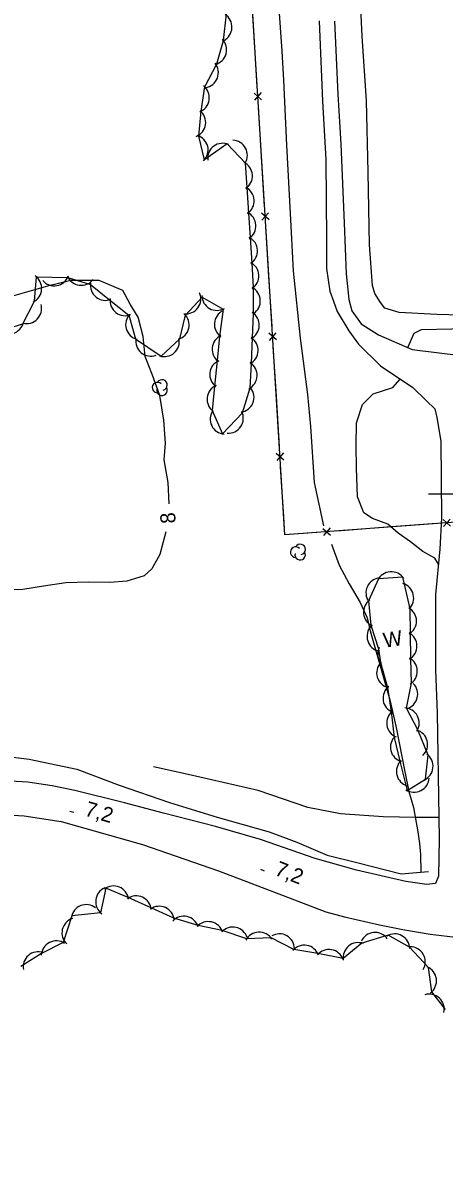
# Model space of a CAD drawing. Extents: x 643342 to 646936, y 5873857 to 5876103.
# Drawn here: x 645909.1 to 645993.2, y 5874668.3 to 5874894 of the extents above; entities that cross this region are included whole.
import ezdxf

# ---------------------------------------------------------------- set-up
doc = ezdxf.new("R2010")
doc.units = 0
for name, color, linetype in [('Niveau 2', 7, 'Continuous'), ('Niveau 21', 7, 'Continuous'), ('Niveau 22', 7, 'Continuous'), ('Niveau 3', 7, 'Continuous'), ('Niveau 33', 7, 'Continuous'), ('Niveau 37', 7, 'Continuous'), ('Niveau 4', 7, 'Continuous'), ('Niveau 44', 7, 'Continuous'), ('Niveau 61', 7, 'Continuous')]:
    doc.layers.add(name, color=color, linetype=linetype)

msp = doc.modelspace()

# ---------------------------------------------------------------- linework, layer by layer
at = {"layer": 'Niveau 2'}
for points in [[(645985.93, 5874829.16), (645987.13, 5874832.05), (645988.65, 5874832.74), (645994.65, 5874832.87), (646001.66, 5874833.42), (646008.42, 5874833.43), (646014.78, 5874834.11), (646019.28, 5874834.02), (646026.81, 5874833.85), (646031.77, 5874833.73), (646037.26, 5874833.59), (646041.91, 5874833.8), (646046.66, 5874834.14), (646048.75, 5874834.28), (646049.86, 5874834.89), (646051.31, 5874836.57), (646051.97, 5874839.3), (646052.28, 5874844.45), (646051.99, 5874857.32), (646051.63, 5874866.57), (646051.17, 5874880.07), (646050.57, 5874891.69), (646049.18, 5874905.3)], [(645938.32, 5874797.98), (645938.1, 5874802.24), (645937.34, 5874806.8), (645937.57, 5874810.09), (645937.27, 5874814.68), (645936.43, 5874819.59), (645935.01, 5874823.64), (645933.5, 5874827.38), (645933.14, 5874831.39), (645932.15, 5874835.23), (645930.55, 5874837.81), (645929.05, 5874840.56), (645924.35, 5874842.57), (645918.74, 5874842.53), (645914.04, 5874841.38), (645905.69, 5874839.04)], [(645991.98, 5874785.95), (645991.26, 5874787.15), (645988.89, 5874788.5), (645986.46, 5874790.43), (645984, 5874792.18), (645981.93, 5874793.96), (645978.87, 5874795.09), (645977.15, 5874796.19), (645975.86, 5874799.43), (645975.65, 5874805.2), (645975.61, 5874809.58), (645975.67, 5874814.14), (645976.84, 5874817.84), (645978.96, 5874819.92), (645982.89, 5874821.18), (645984.38, 5874822.86)], [(645937.66, 5874792.42), (645936.45, 5874787.87), (645934.86, 5874785.01), (645933.33, 5874783.67), (645929.85, 5874782.61), (645926.48, 5874782.31), (645922.16, 5874782.36), (645917.73, 5874782.22), (645913.28, 5874781.55), (645909.12, 5874780.91), (645903.76, 5874780.7)]]:
    msp.add_lwpolyline(points, dxfattribs=at)
at = {"layer": 'Niveau 21'}
for points in [[(645968.22, 5874894.35), (645968.86, 5874878.28), (645969.52, 5874866.66), (645969.69, 5874850.67), (645969.66, 5874844.95), (645970.35, 5874840.44), (645971.09, 5874838.39), (645971.83, 5874836.34), (645974.11, 5874832.53), (645976.06, 5874829.87), (645980.48, 5874825.51)], [(645971.28, 5874894.25), (645971.92, 5874879.71), (645972.57, 5874869.71), (645973.19, 5874854), (645973.61, 5874843.87), (645974.12, 5874838.77), (645974.76, 5874836.47), (645976.59, 5874833.92), (645980.03, 5874831.71), (645986.78, 5874828.8), (645996.44, 5874827.61)], [(645980.48, 5874825.51), (645986.88, 5874821.17), (645989.64, 5874818.56), (645991.28, 5874816.93), (645991.65, 5874815.2), (645992.48, 5874810.47), (645992.6, 5874795.18), (645992.25, 5874788.97), (645991.43, 5874779.92), (645991.42, 5874764.85), (645991.72, 5874756.34), (645992.06, 5874735.44), (645992.13, 5874731.12), (645991.99, 5874723.74), (645991.4, 5874722.29), (645989.67, 5874722.05), (645985.53, 5874722.69), (645975.67, 5874724.91), (645967.43, 5874727.25), (645956.51, 5874731.03), (645947.54, 5874733.67), (645937.17, 5874736.32), (645929.42, 5874738.35), (645919.53, 5874740.8), (645915.01, 5874741.77), (645910.16, 5874742.48), (645902.06, 5874742.95)], [(645734.03, 5874661.49), (645747.15, 5874668.6), (645761.6, 5874677.24), (645774.6, 5874684.96), (645790.1, 5874693.56), (645804.86, 5874701.17), (645820.98, 5874709.46), (645836.3, 5874717.34), (645848.46, 5874723.71), (645854.48, 5874726.13), (645862.13, 5874728.66), (645869.34, 5874730.7), (645876.01, 5874732.23), (645886.75, 5874734.16), (645894.6, 5874735.42), (645900.52, 5874736.08), (645904.96, 5874736.04), (645909.43, 5874735.78), (645916.76, 5874734.66)], [(645916.76, 5874734.66), (645933.01, 5874730.08), (645948.14, 5874724.84), (645961.02, 5874719.91), (645969.56, 5874716.66), (645973.26, 5874715.64), (645980.28, 5874714.04), (645984.91, 5874713.08), (645990.35, 5874712.18), (645996, 5874711.53), (645997.68, 5874710.95), (645999.85, 5874708.53), (646003.25, 5874703.75), (646003.92, 5874701.11), (646005.24, 5874693.02), (646006.92, 5874683.31), (646007.76, 5874673.9), (646008.52, 5874663.89)]]:
    msp.add_lwpolyline(points, dxfattribs=at)
at = {"layer": 'Niveau 22'}
msp.add_lwpolyline([(645992.06, 5874735.44), (645987.5, 5874735.46), (645980.95, 5874735.58), (645972.5, 5874736.15), (645965.98, 5874737.44), (645956.03, 5874740.82), (645942.11, 5874744.04), (645935.22, 5874745.54)], dxfattribs=at)
at = {"layer": 'Niveau 3'}
for p, q in [((645918.54, 5874736.74), (645919.31, 5874736.51)), ((645956.49, 5874725.13), (645957.23, 5874724.84))]:
    msp.add_line(p, q, dxfattribs=at)
at = {"layer": 'Niveau 33'}
msp.add_lwpolyline([(645996.49, 5874835.65), (645991.69, 5874835.78), (645984.19, 5874836.19), (645981.32, 5874837.04), (645980.42, 5874838.14), (645979.35, 5874839.94), (645978.87, 5874841.54), (645978.25, 5874849.68), (645977.96, 5874864.15), (645977.69, 5874878.38), (645976.82, 5874891.29), (645976, 5874908.17)], dxfattribs=at)
at = {"layer": 'Niveau 37'}
for points in [[(646152.66, 5875016.23), (646179.19, 5874807.95), (645961.38, 5874791.81), (645948.36, 5875003.47), (646152.66, 5875016.23)], [(645955.26, 5874891.24), (645954.65, 5874901.22)], [(645955.88, 5874881.26), (645955.26, 5874891.24)], [(645956.75, 5874878.6), (645955.25, 5874879.92)], [(645956.66, 5874880.01), (645955.34, 5874878.51)], [(645956.74, 5874867.28), (645956.12, 5874877.26)], [(645957.35, 5874857.3), (645956.74, 5874867.28)], [(645958.22, 5874854.64), (645956.72, 5874855.97)], [(645958.14, 5874856.06), (645956.81, 5874854.56)], [(645958.21, 5874843.33), (645957.6, 5874853.31)], [(645958.82, 5874833.35), (645958.21, 5874843.33)], [(645959.7, 5874830.69), (645958.2, 5874832.02)], [(645959.61, 5874832.1), (645958.28, 5874830.6)], [(645959.68, 5874819.38), (645959.07, 5874829.36)], [(645960.3, 5874809.4), (645959.68, 5874819.38)], [(645961.17, 5874806.74), (645959.67, 5874808.06)], [(645961.08, 5874808.15), (645959.76, 5874806.65)], [(645961.16, 5874795.42), (645960.54, 5874805.4)], [(645967.74, 5874792.29), (645961.38, 5874791.81), (645961.16, 5874795.42)], [(645992.91, 5874794.86), (645994.43, 5874793.55)], [(645994.33, 5874794.97), (645993.02, 5874793.45)], [(645968.98, 5874793.09), (645970.5, 5874791.78)], [(645970.39, 5874793.19), (645969.09, 5874791.68)], [(645981.71, 5874793.32), (645971.73, 5874792.58)], [(645991.68, 5874794.06), (645981.71, 5874793.32)]]:
    msp.add_lwpolyline(points, dxfattribs=at)
at = {"layer": 'Niveau 4'}
for points in [[(645969.12, 5874793.6), (645967.29, 5874802.24), (645966.56, 5874813.41), (645965.95, 5874819.8), (645964.51, 5874831.04), (645963.13, 5874844.5), (645962.49, 5874855.91), (645961.8, 5874869.54), (645961.16, 5874882.48), (645960.84, 5874888.3), (645959.94, 5874901.56)], [(645970.68, 5874789.94), (645972.2, 5874785.74), (645974.2, 5874782.02), (645976.4, 5874778.32), (645977.81, 5874775.28), (645978.39, 5874772.65), (645980.93, 5874763.81), (645982.31, 5874758.91), (645983.56, 5874753.42), (645985.31, 5874744.55), (645986.12, 5874740.63), (645987, 5874737.44), (645987.89, 5874732.59), (645988.21, 5874730.23), (645988.41, 5874728.05), (645988.5, 5874724.52)], [(645901.77, 5874748.11), (645910.39, 5874747.08), (645919.89, 5874745.07), (645928.32, 5874741.92), (645938.4, 5874738.43), (645947.86, 5874735.48), (645958.25, 5874732.59), (645963.78, 5874730.53), (645969.82, 5874727.92), (645976.02, 5874726.37), (645984.6, 5874724.18), (645990.04, 5874724.66)]]:
    msp.add_lwpolyline(points, dxfattribs=at)
at = {"layer": 'Niveau 44'}
for points in [[(645904.52, 5874832.49), (645909.17, 5874833.88), (645911.46, 5874838.42), (645911.85, 5874843.26), (645918.09, 5874843.15), (645922.63, 5874841.74), (645926.4, 5874838.69), (645930.27, 5874835.61), (645931.58, 5874830.93), (645936.69, 5874827.44), (645940.46, 5874830.92), (645941.57, 5874835.65), (645944.86, 5874839.24), (645949.08, 5874836.84), (645948.34, 5874831.39), (645947.91, 5874826.56), (645947.38, 5874821.44), (645946.87, 5874816.62), (645948.95, 5874811.94), (645952.92, 5874816.12), (645954.49, 5874821.13), (645954.71, 5874825.98), (645954.94, 5874831.12), (645955.15, 5874835.97), (645955.11, 5874841.13), (645954.84, 5874845.98), (645954.54, 5874851.12), (645954.2, 5874855.96), (645953.84, 5874861.09), (645953.51, 5874865.94), (645949.89, 5874869.77), (645945.36, 5874866.64), (645944.22, 5874871.36), (645944.72, 5874876.34), (645945.42, 5874881.14), (645947.82, 5874885.75), (645949.12, 5874890.43), (645949.75, 5874895.71)], [(645985.76, 5874740.82), (645989.43, 5874743.06), (645989.93, 5874747.88), (645987.86, 5874752.96), (645985.6, 5874757.26), (645986.6, 5874762.23), (645986.52, 5874767.08), (645986.44, 5874772.22), (645986.36, 5874777.08), (645985.22, 5874782), (645984.89, 5874783.38), (645980.05, 5874783.04), (645978.07, 5874778.64), (645978.52, 5874773.81), (645980.07, 5874769.06), (645980.45, 5874766.36), (645981.85, 5874761.38), (645982.57, 5874756.58), (645983.14, 5874751.43), (645984.3, 5874746.71), (645985.49, 5874741.86), (645985.76, 5874740.82)], [(645993.38, 5874697.15), (645990.67, 5874700.68), (645990.05, 5874705.5), (645986.25, 5874709.61), (645982, 5874711.95), (645976.72, 5874710.4), (645972.99, 5874707.3), (645967.95, 5874708.29), (645963.17, 5874709.13), (645958.62, 5874711.44), (645953.77, 5874711.24), (645948.86, 5874712.88), (645944.12, 5874713.92), (645939.26, 5874715.34), (645934.84, 5874717.35), (645930.15, 5874719.49), (645925.67, 5874721.35), (645924.63, 5874716.45), (645918.88, 5874715.82), (645917.2, 5874710.5), (645912.86, 5874708.33), (645908.77, 5874705.76)]]:
    msp.add_lwpolyline(points, dxfattribs=at)
for centre, radius, start, end in [((645947.83, 5874893.09), 3, 297.2628, 57.2408), ((645947.83, 5874893.09), 3, 297.2628, 57.2408), ((645947.83, 5874893.09), 3, 297.2628, 57.2408), ((645946.77, 5874888.56), 3, 284.3767, 44.3547), ((645946.77, 5874888.56), 3, 284.3767, 44.3547), ((645946.77, 5874888.56), 3, 284.3767, 44.3547), ((645945.13, 5874884.01), 3, 278.5152, 38.4932), ((645945.13, 5874884.01), 3, 278.5152, 38.4932), ((645945.13, 5874884.01), 3, 278.5152, 38.4932), ((645943.32, 5874879), 3, 291.6549, 51.6328), ((645943.32, 5874879), 3, 291.6549, 51.6328), ((645943.32, 5874879), 3, 291.6549, 51.6328), ((645942.6, 5874874.05), 3, 291.6549, 51.6328), ((645942.6, 5874874.05), 3, 291.6549, 51.6328), ((645942.6, 5874874.05), 3, 291.6549, 51.6328), ((645943.08, 5874868.59), 3, 313.5793, 73.5572), ((645943.08, 5874868.59), 3, 313.5793, 73.5572), ((645943.08, 5874868.59), 3, 313.5793, 73.5572), ((645948.99, 5874866.91), 3, 66.4997, 186.4776), ((645948.99, 5874866.91), 3, 66.4997, 186.4776), ((645948.99, 5874866.91), 3, 66.4997, 186.4776), ((645950.91, 5874867.53), 3, 328.533, 88.5109), ((645950.91, 5874867.53), 3, 328.533, 88.5109), ((645950.91, 5874867.53), 3, 328.533, 88.5109), ((645951.92, 5874863.39), 3, 303.9903, 63.9682), ((645951.92, 5874863.39), 3, 303.9903, 63.9682), ((645951.92, 5874863.39), 3, 303.9903, 63.9682), ((645952.26, 5874858.4), 3, 303.9903, 63.9682), ((645952.26, 5874858.4), 3, 303.9903, 63.9682), ((645952.26, 5874858.4), 3, 303.9903, 63.9682), ((645952.61, 5874853.42), 3, 303.9903, 63.9682), ((645952.61, 5874853.42), 3, 303.9903, 63.9682), ((645952.61, 5874853.42), 3, 303.9903, 63.9682), ((645952.94, 5874848.45), 3, 303.2077, 63.1856), ((645952.94, 5874848.45), 3, 303.2077, 63.1856), ((645952.94, 5874848.45), 3, 303.2077, 63.1856), ((645953.21, 5874843.46), 3, 303.2077, 63.1856), ((645953.21, 5874843.46), 3, 303.2077, 63.1856), ((645953.21, 5874843.46), 3, 303.2077, 63.1856), ((645909.9, 5874840.98), 3, 295.33, 55.308), ((645909.9, 5874840.98), 3, 295.33, 55.308), ((645909.9, 5874840.98), 3, 295.33, 55.308), ((645915.4, 5874844.48), 3, 219.7542, 339.7322), ((645915.4, 5874844.48), 3, 219.7542, 339.7322), ((645915.4, 5874844.48), 3, 219.7542, 339.7322), ((645920.8, 5874844.59), 3, 201.9481, 321.9261), ((645920.8, 5874844.59), 3, 201.9481, 321.9261), ((645920.8, 5874844.59), 3, 201.9481, 321.9261), ((645925.62, 5874841.58), 3, 170.9659, 290.9438), ((645925.62, 5874841.58), 3, 170.9659, 290.9438), ((645925.62, 5874841.58), 3, 170.9659, 290.9438), ((645941.63, 5874838.89), 3, 263.0045, 22.9825), ((645941.63, 5874838.89), 3, 263.0045, 22.9825), ((645941.63, 5874838.89), 3, 263.0045, 22.9825), ((645953.49, 5874838.46), 3, 303.2077, 63.1856), ((645953.49, 5874838.46), 3, 303.2077, 63.1856), ((645953.49, 5874838.46), 3, 303.2077, 63.1856), ((645909.88, 5874836.95), 3, 255.3918, 15.3698), ((645909.88, 5874836.95), 3, 255.3918, 15.3698), ((645909.88, 5874836.95), 3, 255.3918, 15.3698), ((645929.53, 5874838.52), 3, 172.2624, 292.2403), ((645929.53, 5874838.52), 3, 172.2624, 292.2403), ((645929.53, 5874838.52), 3, 172.2624, 292.2403), ((645947.84, 5874839.57), 3, 180.4297, 300.4076), ((645947.84, 5874839.57), 3, 180.4297, 300.4076), ((645947.84, 5874839.57), 3, 180.4297, 300.4076), ((645932.63, 5874833.75), 3, 135.6691, 255.6471), ((645932.63, 5874833.75), 3, 135.6691, 255.6471), ((645932.63, 5874833.75), 3, 135.6691, 255.6471), ((645939.3, 5874833.69), 3, 286.7798, 46.7577), ((645939.3, 5874833.69), 3, 286.7798, 46.7577), ((645939.3, 5874833.69), 3, 286.7798, 46.7577), ((645950.32, 5874833.8), 3, 114.9218, 234.8998), ((645950.32, 5874833.8), 3, 114.9218, 234.8998), ((645950.32, 5874833.8), 3, 114.9218, 234.8998), ((645953.28, 5874833.62), 3, 297.49, 57.4679), ((645953.28, 5874833.62), 3, 297.49, 57.4679), ((645953.28, 5874833.62), 3, 297.49, 57.4679), ((645906.34, 5874834.87), 3, 226.6735, 346.6514), ((645906.34, 5874834.87), 3, 226.6735, 346.6514), ((645906.34, 5874834.87), 3, 226.6735, 346.6514), ((645934.65, 5874830.45), 3, 170.6479, 290.6258), ((645934.65, 5874830.45), 3, 170.6479, 290.6258), ((645934.65, 5874830.45), 3, 170.6479, 290.6258), ((645937.34, 5874830.36), 3, 251.5009, 11.4789), ((645937.34, 5874830.36), 3, 251.5009, 11.4789), ((645937.34, 5874830.36), 3, 251.5009, 11.4789), ((645949.88, 5874828.82), 3, 114.9218, 234.8998), ((645949.88, 5874828.82), 3, 114.9218, 234.8998), ((645949.88, 5874828.82), 3, 114.9218, 234.8998), ((645953.06, 5874828.62), 3, 297.49, 57.4679), ((645953.06, 5874828.62), 3, 297.49, 57.4679), ((645953.06, 5874828.62), 3, 297.49, 57.4679), ((645949.41, 5874823.81), 3, 113.9485, 233.9264), ((645949.41, 5874823.81), 3, 113.9485, 233.9264), ((645949.41, 5874823.81), 3, 113.9485, 233.9264), ((645952.84, 5874823.63), 3, 297.49, 57.4679), ((645952.84, 5874823.63), 3, 297.49, 57.4679), ((645952.84, 5874823.63), 3, 297.49, 57.4679), ((645935.98, 5874821.18), 1.05, 44.1154, 269.804), ((645936.88, 5874821.71), 1.05, 282.2692, 149.7263), ((645948.88, 5874818.84), 3, 113.9485, 233.9264), ((645948.88, 5874818.84), 3, 113.9485, 233.9264), ((645948.88, 5874818.84), 3, 113.9485, 233.9264), ((645936.88, 5874820.66), 1.05, 166.9369, 29.6212), ((645952.23, 5874819.24), 3, 277.7816, 37.7595), ((645952.23, 5874819.24), 3, 277.7816, 37.7595), ((645952.23, 5874819.24), 3, 277.7816, 37.7595), ((645949.5, 5874814.89), 3, 145.482, 265.4599), ((645949.5, 5874814.89), 3, 145.482, 265.4599), ((645949.5, 5874814.89), 3, 145.482, 265.4599), ((645950.1, 5874815.08), 3, 266.1343, 26.1122), ((645950.1, 5874815.08), 3, 266.1343, 26.1122), ((645950.1, 5874815.08), 3, 266.1343, 26.1122), ((645964.43, 5874788.91), 1.05, 282.2692, 149.7263), ((645963.53, 5874788.38), 1.05, 44.1154, 269.804), ((645964.43, 5874787.86), 1.05, 166.9369, 29.6212), ((645980.55, 5874780.25), 3, 95.1112, 215.0891), ((645980.55, 5874780.25), 3, 95.1112, 215.0891), ((645980.55, 5874780.25), 3, 95.1112, 215.0891), ((645982.59, 5874781.45), 3, 34.0714, 154.0494), ((645982.59, 5874781.45), 3, 34.0714, 154.0494), ((645982.59, 5874781.45), 3, 34.0714, 154.0494), ((645984.07, 5874779.23), 3, 313.5818, 73.5598), ((645984.07, 5874779.23), 3, 313.5818, 73.5598), ((645984.07, 5874779.23), 3, 313.5818, 73.5598), ((645980.05, 5874776.39), 3, 125.3144, 245.2924), ((645980.05, 5874776.39), 3, 125.3144, 245.2924), ((645980.05, 5874776.39), 3, 125.3144, 245.2924), ((645984.63, 5874774.62), 3, 300.9414, 60.9194), ((645984.63, 5874774.62), 3, 300.9414, 60.9194), ((645984.63, 5874774.62), 3, 300.9414, 60.9194), ((645980.76, 5874771.58), 3, 130.4514, 250.4294), ((645980.76, 5874771.58), 3, 130.4514, 250.4294), ((645980.76, 5874771.58), 3, 130.4514, 250.4294), ((645984.71, 5874769.62), 3, 300.9414, 60.9194), ((645984.71, 5874769.62), 3, 300.9414, 60.9194), ((645984.71, 5874769.62), 3, 300.9414, 60.9194), ((645982.91, 5874768.09), 3, 155.1287, 219.2992), ((645982.91, 5874768.09), 3, 155.1287, 219.2992), ((645982.91, 5874768.09), 3, 155.1287, 219.2992), ((645982.68, 5874764.29), 3, 136.8898, 256.8678), ((645982.68, 5874764.29), 3, 136.8898, 256.8678), ((645982.68, 5874764.29), 3, 136.8898, 256.8678), ((645984.79, 5874764.62), 3, 300.9414, 60.9194), ((645984.79, 5874764.62), 3, 300.9414, 60.9194), ((645984.79, 5874764.62), 3, 300.9414, 60.9194), ((645983.95, 5874759.24), 3, 128.5117, 248.4897), ((645983.95, 5874759.24), 3, 128.5117, 248.4897), ((645983.95, 5874759.24), 3, 128.5117, 248.4897), ((645984.87, 5874760.04), 3, 285.2965, 45.2745), ((645984.87, 5874760.04), 3, 285.2965, 45.2745), ((645984.87, 5874760.04), 3, 285.2965, 45.2745), ((645984.69, 5874754.3), 3, 128.5117, 248.4897), ((645984.69, 5874754.3), 3, 128.5117, 248.4897), ((645984.69, 5874754.3), 3, 128.5117, 248.4897), ((645985.17, 5874754.29), 3, 327.6951, 87.673), ((645985.17, 5874754.29), 3, 327.6951, 87.673), ((645985.17, 5874754.29), 3, 327.6951, 87.673), ((645985.43, 5874749.49), 3, 133.8311, 253.8091), ((645985.43, 5874749.49), 3, 133.8311, 253.8091), ((645985.43, 5874749.49), 3, 133.8311, 253.8091), ((645986.84, 5874750), 3, 313.8317, 73.8097), ((645986.84, 5874750), 3, 313.8317, 73.8097), ((645986.84, 5874750), 3, 313.8317, 73.8097), ((645987.92, 5874745.65), 3, 294.097, 54.0749), ((645987.92, 5874745.65), 3, 294.097, 54.0749), ((645987.92, 5874745.65), 3, 294.097, 54.0749), ((645986.62, 5874744.64), 3, 133.8311, 253.8091), ((645986.62, 5874744.64), 3, 133.8311, 253.8091), ((645986.62, 5874744.64), 3, 133.8311, 253.8091), ((645987.15, 5874743.49), 3, 236.5526, 356.5305), ((645987.15, 5874743.49), 3, 236.5526, 356.5305), ((645987.15, 5874743.49), 3, 236.5526, 356.5305), ((645926.66, 5874718.66), 3, 113.4098, 233.3877), ((645926.66, 5874718.66), 3, 113.4098, 233.3877), ((645926.66, 5874718.66), 3, 113.4098, 233.3877), ((645927.24, 5874718.79), 3, 7.5654, 127.5434), ((645927.24, 5874718.79), 3, 7.5654, 127.5434), ((645927.24, 5874718.79), 3, 7.5654, 127.5434), ((645921.78, 5874715.07), 3, 51.5013, 171.4792), ((645921.78, 5874715.07), 3, 51.5013, 171.4792), ((645921.78, 5874715.07), 3, 51.5013, 171.4792), ((645931.77, 5874716.81), 3, 5.571, 125.5489), ((645931.77, 5874716.81), 3, 5.571, 125.5489), ((645931.77, 5874716.81), 3, 5.571, 125.5489), ((645936.32, 5874714.74), 3, 5.571, 125.5489), ((645936.32, 5874714.74), 3, 5.571, 125.5489), ((645936.32, 5874714.74), 3, 5.571, 125.5489), ((645941.23, 5874712.75), 3, 17.5727, 137.5507), ((645941.23, 5874712.75), 3, 17.5727, 137.5507), ((645941.23, 5874712.75), 3, 17.5727, 137.5507), ((645919.94, 5874712.43), 3, 107.5518, 227.5297), ((645919.94, 5874712.43), 3, 107.5518, 227.5297), ((645919.94, 5874712.43), 3, 107.5518, 227.5297), ((645946.11, 5874711.68), 3, 17.5727, 137.5507), ((645946.11, 5874711.68), 3, 17.5727, 137.5507), ((645946.11, 5874711.68), 3, 17.5727, 137.5507), ((645951, 5874710.6), 3, 17.5727, 137.5507), ((645951, 5874710.6), 3, 17.5727, 137.5507), ((645951, 5874710.6), 3, 17.5727, 137.5507), ((645956.27, 5874709.58), 3, 32.422, 152.4), ((645956.27, 5874709.58), 3, 32.422, 152.4), ((645956.27, 5874709.58), 3, 32.422, 152.4), ((645960.3, 5874709.24), 3, 0.8113, 120.7892), ((645960.3, 5874709.24), 3, 0.8113, 120.7892), ((645960.3, 5874709.24), 3, 0.8113, 120.7892), ((645979.36, 5874709.52), 3, 35.4765, 155.4544), ((645979.36, 5874709.52), 3, 35.4765, 155.4544), ((645979.36, 5874709.52), 3, 35.4765, 155.4544), ((645983.28, 5874709.23), 3, 1.2415, 121.2195), ((645983.28, 5874709.23), 3, 1.2415, 121.2195), ((645983.28, 5874709.23), 3, 1.2415, 121.2195), ((645915.82, 5874707.84), 3, 56.6489, 176.6269), ((645915.82, 5874707.84), 3, 56.6489, 176.6269), ((645915.82, 5874707.84), 3, 56.6489, 176.6269), ((645965.26, 5874706.97), 3, 20.069, 140.047), ((645965.26, 5874706.97), 3, 20.069, 140.047), ((645965.26, 5874706.97), 3, 20.069, 140.047), ((645970.18, 5874706.11), 3, 20.069, 140.047), ((645970.18, 5874706.11), 3, 20.069, 140.047), ((645970.18, 5874706.11), 3, 20.069, 140.047), ((645975.99, 5874707.49), 3, 69.7886, 189.7665), ((645975.99, 5874707.49), 3, 69.7886, 189.7665), ((645975.99, 5874707.49), 3, 69.7886, 189.7665), ((645986.36, 5874706.66), 3, 329.9756, 89.9535), ((645986.36, 5874706.66), 3, 329.9756, 89.9535), ((645986.36, 5874706.66), 3, 329.9756, 89.9535), ((645912.2, 5874705.66), 3, 70.8184, 190.7963), ((645912.2, 5874705.66), 3, 70.8184, 190.7963), ((645912.2, 5874705.66), 3, 70.8184, 190.7963), ((645988.61, 5874702.86), 3, 307.4007, 67.3786), ((645988.61, 5874702.86), 3, 307.4007, 67.3786), ((645988.61, 5874702.86), 3, 307.4007, 67.3786), ((645990.15, 5874697.23), 3, 346.7234, 106.7014), ((645990.15, 5874697.23), 3, 346.7234, 106.7014), ((645990.15, 5874697.23), 3, 346.7234, 106.7014)]:
    msp.add_arc(centre, radius, start, end, dxfattribs=at)
at = {"layer": 'Niveau 61'}
msp.add_lwpolyline([(645990, 5874800), (646000, 5874800), (646010, 5874800)], dxfattribs=at)

# ---------------------------------------------------------------- texts
at = {"layer": 'Niveau 2'}
msp.add_text('8', height=3, rotation=94.0956, dxfattribs=at).set_placement((645939.63, 5874794.16))
at = {"layer": 'Niveau 3'}
for rotation, p in [(343.5381, (645921.29, 5874735.88)), (338.7837, (645959.16, 5874724.05))]:
    msp.add_text('7,2  ', height=3, rotation=rotation, dxfattribs=at).set_placement(p)
at = {"layer": 'Niveau 44'}
msp.add_text('W', height=3, rotation=8.9405, dxfattribs=at).set_placement((645981.24, 5874769.27))

doc.saveas('drawing.dxf')
